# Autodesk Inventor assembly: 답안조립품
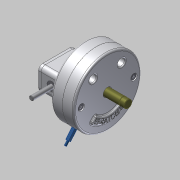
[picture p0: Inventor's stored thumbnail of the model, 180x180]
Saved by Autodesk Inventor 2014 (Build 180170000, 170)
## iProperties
Created: 2015-04
Part Number: 답안조립품
Document SubType Name: Assembly
Designer: Administrator
Author: Administrator
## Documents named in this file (15)
- C:\Documents and Settings\Administrator\바탕 화면\350406V1015\답안조립품.iam
- C:\Documents and Settings\Administrator\바탕 화면\350406V1015\본체.ipt
- C:\Documents and Settings\Administrator\바탕 화면\350406V1015\커버.ipt
- C:\Documents and Settings\Administrator\바탕 화면\350406V1015\가변스프링.ipt
- C:\Documents and Settings\Administrator\바탕 화면\350406V1015\축.ipt
- C:\Documents and Settings\Administrator\바탕 화면\350406V1015\멈춤링.ipt
- C:\Documents and Settings\Administrator\바탕 화면\350406V1015\베어링62_22.ipt
- C:\Documents and Settings\Administrator\바탕 화면\350406V1015\M 10 x 35.ipt
- C:\Documents and Settings\Administrator\바탕 화면\350406V1015\커버2.ipt
- C:\Documents and Settings\Administrator\바탕 화면\350406V1015\M 5 x 12.ipt
- C:\Documents and Settings\Administrator\바탕 화면\350406V1015\슬라이더2.ipt
- C:\Documents and Settings\Administrator\바탕 화면\350406V1015\슬라이더.ipt
- C:\Documents and Settings\Administrator\바탕 화면\350406V1015\평행핀.ipt
- C:\Documents and Settings\Administrator\바탕 화면\350406V1015\슬라이더3.ipt
- C:\Documents and Settings\Administrator\바탕 화면\350406V1015\부시.ipt
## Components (6 placed, 4 different names)
1. M 10 x 35:1
2. M 10 x 35:2
3. M 5 x 12:1
4. M 5 x 12:2
5. KS B 1320 B B 5 x  20:1 — 플러쉬:1
6. 가변스프링:1
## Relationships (1: Flush 1)
- 플러쉬:1 [Flush]: KS B 1320 B B 5 x  20:1
